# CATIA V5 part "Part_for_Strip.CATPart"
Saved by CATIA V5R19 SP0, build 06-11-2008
Publications: "Work_Solid", "RotationLine", "Join_Contours"
Bounding box of the stored display mesh (mm): x -13 to 53.421, y -56.508 to 56.212, z -6.847 to 23.79
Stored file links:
  C:\Documents and Settings\dpv\Desktop\SL9_test_14th_august\everything_done\Part_for_Strip.CATPart
  D:\Program Files\Dassault Systemes\SL9_5.0\intel_a\resources\graphic\Powercopies\PowerCopy_3D_Stamp_unfolding.CATPart
  D:\Program Files\Dassault Systemes\SL9_5.0\intel_a\resources\graphic\Powercopies\PowerCopyRib_Removing.CATPart
  C:\Program Files\Dassault Systemes\Strip Layout Design\intel_a\resources\graphic\Powercopies\PowerCopyRib_Removing.CATPart
  C:\Program Files\Dassault Systemes\Strip Layout Design\intel_a\resources\graphic\Powercopies\PowerCopy_3D_Stamp_unfolding.CATPart
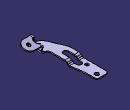
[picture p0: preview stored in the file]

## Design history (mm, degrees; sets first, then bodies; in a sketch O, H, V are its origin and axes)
External parameters (linked from other documents)
  `External.Part Thickness` = 2 mm
SheetMetalParameters1: BendRadius 4, ReliefAxialLength 2, ReliefRadialLength 1, MinimumBendRadius 0, Thickness 2, KFactor 0.400515 {= log(min(100,max(20*SheetMetalParameters1.BendRadius,SheetMetalParameters1.Thickness)/SheetMetalParameters1.Thickness))/log(100)/2}
Set1 "Line"
  Point1: type Between, Ratio 0.5, SecondPoint vertex [face of Solid1 | face of Solid1 | face of Solid1 | face of Solid1], FirstPoint vertex [face of Solid1 | face of Solid1 | face of Solid1 | face of Solid1]
  Line1: type PtDir, Direction face of Solid1, Start 0, End 20, RefPoint Point1
Set2 "IsolatedSurface"
  Extract1 "Reference Face": ExtractElem face of Solid1
  Join1 "SurroundingLine": Elements (edge [face of Solid1 | face of Solid1]; edge [face of Solid1 | face of Solid1]; edge [face of Solid1 | face of Solid1]; edge [face of Solid1 | face of Solid1])
  Split1 "Face to remove": ToCut Extract1, Cutting Join1
Set3 "Isolated Stamp Contours"
  Join2 "Joint_Contours": Elements (Join1; Extract2; Extract4)
Set4 "IsolatedSurface"
  Extract2 "SurroundingLine": ExtractElem edge [face of Solid1 | face of Solid1]
  Extract3 "Basis surface": ExtractElem face of Solid1
  Split2 "Removing surface": ToCut Extract3, Cutting Extract2
Set5 "IsolatedSurface"
  Extract4 "SurroundingLine": ExtractElem edge [face of Solid1 | face of Solid1]
  Extract5 "Basis surface": ExtractElem face of Solid1
  Split3 "Removing surface": ToCut Extract5, Cutting Extract4
Body1 (main body)
  Solid1: solid without history
  Body2 "Volume"
    ThickSurface1 "Volume to remove": Surface Split1, BotOffset 0.2 {= `External.Part Thickness` *0.1}, TopOffset 2.2 {= `External.Part Thickness` *1.1}
  Remove1: tool Body2
  Body3 "Body to remove"
    ThickSurface2 "Volume to remove": Surface Split2, BotOffset 0, TopOffset 2.005 {= `External.Part Thickness` +0.005mm}
  Remove2: tool Body3
  Body4 "Body to remove"
    ThickSurface3 "Volume to remove": Surface Split3, BotOffset 0, TopOffset 2.005 {= `External.Part Thickness` +0.005mm}
  Remove3: tool Body4
  Recognize1: Recognize_ReferenceFace face of Solid1, KFacteur 0.400515 {= SheetMetalParameters1.KFactor}
Body5 "Isolated"
  ThickSurface4 "Isolated Rib": Surface Split1, BotOffset 0, TopOffset 2 {= `External.Part Thickness`}
Body6 "Isolated"
  ThickSurface5 "Isolated Stamp": Surface Split2, BotOffset 0, TopOffset 2 {= `External.Part Thickness`}
Body7 "Isolated"
  ThickSurface6 "Isolated Stamp": Surface Split3, BotOffset 0, TopOffset 2 {= `External.Part Thickness`}
Body8 "SolidToPublish"
  Solid2: CATSmSolid_Thickness 2, linked copy from another document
